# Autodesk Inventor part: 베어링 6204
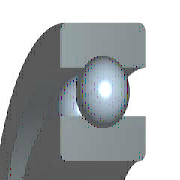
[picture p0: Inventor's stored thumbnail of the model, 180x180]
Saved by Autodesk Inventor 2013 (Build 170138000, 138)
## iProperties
IsCustomPart: 1
Created: 2012-02
Part Number: 베어링 6204
Material: 강철, 연강
Description: 단열 볼 베어링
Document SubType Name: Modeling
Standard: JIS B 1521
Designer: mdu-01
Standards Organization: JIS
Language: ko-KR
Size Designation: SKF 6204
Categories: <MemberInstance><Categories><Category DisplayName="샤프트 부품" InternalName="7f7aeb1f-a693-4053-b835-cee3144e0d98" Mnemonic="SHFT"><Category DisplayName="베어링" Inter
Density: 7.86 g/cm^3
Author: mdu-01
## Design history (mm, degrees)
node "WorkPoint1"
node "WorkAxis1"
node "WorkPlane3"
node "WorkPlane4"
node "WorkPoint2"
body "Solid1"
node "스케치1"
revolve "회전1" stored, may be unused: angle "d6" = 360 deg
revolve "회전2" stored, may be unused: angle "d10" = 360 deg
node "스케치4"
revolve "회전3" stored, may be unused: angle "d16" = 360 deg
pattern_circular "원형 배열1" dims "d17" = 66.03704 (= msp_pocet), angle "d19" = 360 deg
fillet "모깎기1" dims "d20" = 1 (= r)
sketch "스케치2"
  geometry: L1 (10, 14)-(23.5, 14); L2 (10, 0)-(10, 14); L3 (23.5, 0)-(10, 0); L4 (23.5, 14)-(23.5, 0); L5 (0, 0)-(0, 20); L6 (0, 0)-(0, 20); L7 (-7.2, 0)-(43.2, 0) reference
  constraints: 12 end point, 3 vertical, 2 horizontal, 1 collinear, 1 other
  dimensions: "d1" = 20 diameter of L1.start L5 (= Diam); "d3" = 47 diameter of L1.end L5 (= DD); "d5" = 14 distance of L2.start L1.start (= msp_mdtd2)
sketch "스케치3"
  geometry: L1 (19.18, 14)-(19.18, 10.24); L2 (14.32, 14)-(19.18, 14); L3 (14.32, 10.24)-(14.32, 14); L4 (14.32, 0)-(14.32, 3.76); L5 (19.18, 0)-(14.32, 0); L6 (19.18, 3.76)-(19.18, 0); L7 (23.5, 0)-(-23.5, 0) reference; L8 (23.5, 14)-(-23.5, 14) reference; L9 (0, -42.29)-(0, 61.29); L10 (0, 82.007)-(0, -63.007) reference; A1 r 4.05 centre (16.75, 7) between (19.18, 3.76) and (19.18, 10.24); A2 r 4.05 centre (16.75, 7) between (14.32, 10.24) and (14.32, 3.76)
  constraints: 14 end point, 4 collinear, 4 point on circle, 4 vertical, 2 centre point, 2 concentric, 2 horizontal, 2 point on line
  dimensions: "d9" = 8.1 diameter of A1 (= msp_mdtd6); "d21" = 14.32 distance between parallel lines of L9 L4 (= 0.5 x msp_d1); "d22" = 16.75 distance from line of L9 A1.centre (= 0.5 x msp_ds); "d23" = 19.18 distance between parallel lines of L9 L6 (= 0.5 x msp_dd1)
sketch "스케치5"
  geometry: L1 (16.75, 2.95)-(16.75, 11.05); L2 (19.18, 0)-(-19.18, 0) reference; L3 (16.75, 2.95)-(16.75, 11.05); A1 r 4.05 centre (16.75, 7) between (16.75, 2.95) and (16.75, 11.05); A2 r 4.05 centre (16.75, 7) between (19.18, 3.76) and (19.18, 10.24) reference
  constraints: 4 end point, 2 point on circle, 1 centre point, 1 concentric, 1 vertical
  dimensions: "d13" = 0 horizontal distance of A1.centre L1.start; "d15" = 8.1001 diameter of A1 (computed from msp_mdtd6)
other parameters: "Diam" = 20 [user parameter; used in 3 equation terms], "DD" = 47 [user parameter; used in 3 equation terms], "B" = 14 [user parameter; used in 1 equation term], "r" = 1 [user parameter; used in 1 equation term], "msp_ds" = 33.5 (= 0.5 x Diam + 0.5 x DD) [user parameter; used in 5 equation terms], "msp_d0" = 8.1 (= -0.3 x Diam + 0.3 x DD) [user parameter; used in 4 equation terms], "msp_d1" = 28.64 (= msp_ds - 0.6 x msp_d0) [user parameter; used in 1 equation term], "msp_dd1" = 38.36 (= msp_ds + 0.6 x msp_d0) [user parameter; used in 1 equation term], "msp_pom" = 50.25 (= 1.5 x msp_ds) [user parameter; used in 1 equation term], "msp_mdtd2" = 14 (= B) [user parameter; used in 3 equation terms], "msp_mdtd4" = 33.5 (= msp_ds) [user parameter], "msp_mdtd6" = 8.1 (= msp_d0) [user parameter; used in 2 equation terms], "msp_mdtd7" = 7 (= 0.5 x msp_mdtd2) [user parameter], "msp_pocet" = 66.03704 (computed from msp_d0, msp_pom) [user parameter; used in 1 equation term], "d2" = 72 (derived), "d4" = 19 (derived), "d7" = 0, "d8" = 15.6 (derived), "d11" = -14 (computed from msp_mdtd2), "d12" = 0 (derived), "d14" = 15.6001 (derived), "d26" = 0, "d27" = 0, "d28" = 0, "d29" = 0, "d30" = 0
